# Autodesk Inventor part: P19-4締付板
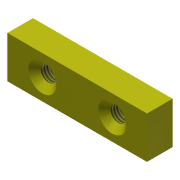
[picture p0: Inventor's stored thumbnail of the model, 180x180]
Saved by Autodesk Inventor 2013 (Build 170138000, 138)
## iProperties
Created: 2008-07
Part Number: P19-4締付板
Document SubType Name: Modeling
Designer: y-shimohigashi
Density: 1 g/cm^3
Stock Number: P19-4締付板
Material: 一般
Author: y-shimohigashi
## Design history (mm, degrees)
sketch "スケッチ1"
  geometry: L1 (-30, 5.5)-(30, 5.5); L2 (30, 5.5)-(30, -5.5); L3 (30, -5.5)-(-30, -5.5); L4 (-30, -5.5)-(-30, 5.5); L5 (30, 5.5)-(-30, -5.5); 2 further points
  constraints: 10 end point, 2 parallel, 1 coincident, 1 horizontal, 1 midpoint, 1 perpendicular
  dimensions: "d0" = 11 distance of L1.end L2.end; "d1" = 60 distance of L2.end L3.end
extrude "押し出し1" new body sketch "スケッチ1" distance "d2" = 18; taper "d3" = 0 deg
sketch "スケッチ2"
  geometry: L1 (30, -3.6)-(30, 21.6) reference; L2 (60, 0)-(60, 18) reference; 3 further points
  constraints: 1 horizontal alignment, 1 midpoint, 1 symmetric about line
  dimensions: "d4" = 30 distance of point (45, 9) point (15, 9)
hole "穴1" sketch "スケッチ2" at (15, 9), (45, 9) diameter "d5" = 6.647; stored, may be unused: countersink angle "d9" = 90 deg, drill point angle "d11" = 118 deg; dims "d6" = 6, "d7" = 12, "d8" = 2, "d10" = 8
node "ソリッド1"
node "ソリッド ボディ"
node "サーフェス ボディ"
